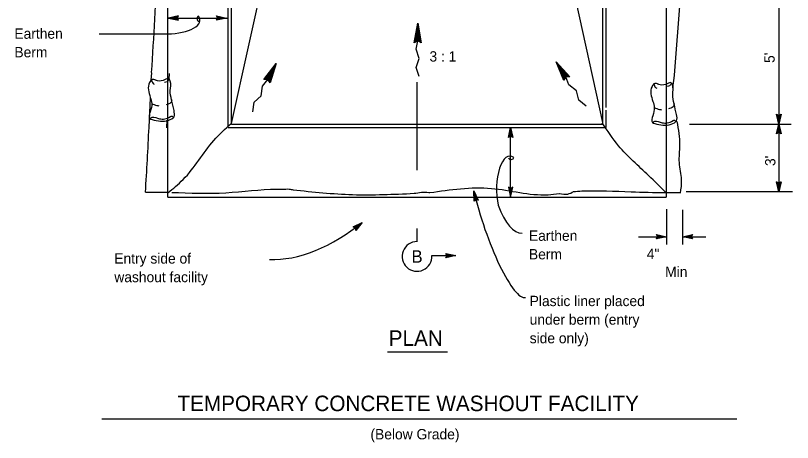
# Model space of a CAD drawing. Extents: x 6708826 to 6711089, y 1868571 to 1869537.
# Drawn here: x 6708832 to 6709283.4, y 1868571 to 1868819.1 of the extents above; entities that cross this region are included whole.
import ezdxf

# ---------------------------------------------------------------- set-up
doc = ezdxf.new("R2010")
doc.units = 0
for name, color, linetype in [('1 Control', 7, 'Continuous'), ('56 Stg 3 Anno', 7, 'Continuous'), ('57 Undefined', 7, 'Continuous'), ('60 Nongeo Data', 7, 'Continuous')]:
    doc.layers.add(name, color=color, linetype=linetype)

msp = doc.modelspace()

# ---------------------------------------------------------------- linework, layer by layer
at = {"layer": '1 Control'}
for p, q in [((6709274.17, 1868722.46), (6709274.17, 1868722.46)), ((6709276.73, 1868722.46), (6709276.73, 1868722.46)), ((6709098.33, 1868717.18), (6709098.33, 1868717.18)), ((6709275.45, 1868716.7), (6709275.45, 1868716.7)), ((6709098.34, 1868711.27), (6709098.34, 1868711.27)), ((6709100.84, 1868711.84), (6709100.84, 1868711.84)), ((6709204.39, 1868691.86), (6709204.39, 1868691.86)), ((6709225.36, 1868691.85), (6709225.36, 1868691.85)), ((6709204.39, 1868689.29), (6709204.39, 1868689.29)), ((6709210.15, 1868690.57), (6709210.15, 1868690.57)), ((6709219.6, 1868690.57), (6709219.6, 1868690.57)), ((6709225.36, 1868689.28), (6709225.36, 1868689.28))]:
    msp.add_line(p, q, dxfattribs=at)
for points in [[(6709276.73, 1868722.46), (6709275.45, 1868716.7), (6709274.17, 1868722.46), (6709274.51, 1868722.25), (6709275.44, 1868718.03), (6709276.39, 1868722.25), (6709276.05, 1868722.05), (6709275.45, 1868719.35), (6709274.85, 1868722.05), (6709275.19, 1868721.84), (6709275.45, 1868720.67), (6709275.71, 1868721.85), (6709275.45, 1868721.69), (6709274.17, 1868722.46), (6709275.45, 1868721.69)], [(6709098.34, 1868711.27), (6709098.33, 1868717.18), (6709100.84, 1868711.84), (6709100.46, 1868711.96), (6709098.63, 1868715.87), (6709098.63, 1868711.55), (6709098.91, 1868711.82), (6709098.91, 1868714.59), (6709100.09, 1868712.09), (6709099.71, 1868712.21), (6709099.2, 1868713.29), (6709099.2, 1868712.09), (6709099.43, 1868712.31), (6709100.84, 1868711.84), (6709099.43, 1868712.31)], [(6709204.39, 1868691.86), (6709210.15, 1868690.57), (6709204.39, 1868689.29), (6709204.6, 1868689.63), (6709208.82, 1868690.57), (6709204.6, 1868691.52), (6709204.8, 1868691.18), (6709207.5, 1868690.57), (6709204.8, 1868689.97), (6709205.01, 1868690.31), (6709206.17, 1868690.57), (6709205, 1868690.83), (6709205.16, 1868690.57), (6709204.39, 1868689.29), (6709205.16, 1868690.57)], [(6709225.36, 1868689.28), (6709219.6, 1868690.57), (6709225.36, 1868691.85), (6709225.15, 1868691.51), (6709220.93, 1868690.57), (6709225.15, 1868689.62), (6709224.95, 1868689.96), (6709222.25, 1868690.57), (6709224.95, 1868691.17), (6709224.74, 1868690.83), (6709223.58, 1868690.57), (6709224.75, 1868690.31), (6709224.59, 1868690.57), (6709225.36, 1868691.85), (6709224.59, 1868690.57)]]:
    msp.add_lwpolyline(points, close=True, dxfattribs=at)
for centre, major_axis in [((6708938.43, 1868817.2), (0.09, -1.51)), ((6709119.92, 1868736.43), (1.51, 0.09))]:
    msp.add_ellipse(centre, major_axis=major_axis, ratio=0.650992, start_param=3.141593, end_param=6.283185, dxfattribs=at)
at = {"layer": '56 Stg 3 Anno'}
for p, q in [((6709275.45, 1868833.28), (6709275.45, 1868756.03)), ((6708926.63, 1868818.88), (6708920.87, 1868817.59)), ((6708926.42, 1868818.54), (6708922.19, 1868817.59)), ((6708926.2, 1868818.19), (6708923.52, 1868817.59)), ((6708926.03, 1868817.86), (6708924.85, 1868817.59)), ((6708925.86, 1868817.59), (6708926.63, 1868818.88)), ((6708926.63, 1868818.88), (6708926.63, 1868818.88)), ((6708949.46, 1868817.59), (6708948.69, 1868818.88)), ((6708948.69, 1868818.88), (6708948.69, 1868818.88)), ((6708948.69, 1868818.88), (6708954.45, 1868817.59)), ((6708948.9, 1868818.54), (6708953.13, 1868817.59)), ((6708949.13, 1868818.19), (6708951.8, 1868817.59)), ((6708949.3, 1868817.86), (6708950.48, 1868817.59)), ((6708920.43, 1868817.59), (6708955.21, 1868817.59)), ((6708920.87, 1868817.59), (6708920.87, 1868817.59)), ((6708920.87, 1868817.59), (6708926.63, 1868816.31)), ((6708922.2, 1868817.59), (6708926.4, 1868816.66)), ((6708923.52, 1868817.59), (6708926.23, 1868816.99)), ((6708924.85, 1868817.59), (6708926.01, 1868817.34)), ((6708926.63, 1868816.31), (6708925.86, 1868817.59)), ((6708926.63, 1868816.31), (6708926.63, 1868816.31)), ((6708954.45, 1868817.59), (6708948.69, 1868816.31)), ((6708948.69, 1868816.31), (6708949.46, 1868817.59)), ((6708948.69, 1868816.31), (6708948.69, 1868816.31)), ((6708953.12, 1868817.59), (6708948.92, 1868816.66)), ((6708951.8, 1868817.59), (6708949.09, 1868816.99)), ((6708950.48, 1868817.59), (6708949.32, 1868817.34)), ((6708954.45, 1868817.59), (6708954.45, 1868817.59)), ((6709063.57, 1868803.19), (6709065.61, 1868814.73)), ((6709065.61, 1868814.73), (6709067.65, 1868803.19)), ((6709064.11, 1868803.51), (6709065.61, 1868811.97)), ((6709064.66, 1868803.82), (6709065.61, 1868809.23)), ((6709065.61, 1868811.97), (6709067.11, 1868803.51)), ((6709065.61, 1868809.23), (6709066.56, 1868803.82)), ((6708880.5, 1868808.48), (6708920.43, 1868808.48)), ((6709065.61, 1868804.37), (6709063.57, 1868803.19)), ((6709065.21, 1868804.14), (6709065.61, 1868806.43)), ((6709065.61, 1868806.43), (6709066.01, 1868804.14)), ((6709067.65, 1868803.19), (6709065.61, 1868804.37)), ((6708976.21, 1868781.88), (6708983.33, 1868791.19)), ((6708983.33, 1868791.19), (6708979.83, 1868780)), ((6709150.57, 1868781.35), (6709146.1, 1868792.18)), ((6709146.1, 1868792.18), (6709154.01, 1868783.53)), ((6708976.84, 1868781.91), (6708982.06, 1868788.74)), ((6708977.47, 1868781.94), (6708980.8, 1868786.31)), ((6708980.8, 1868786.31), (6708979.16, 1868781.06)), ((6708982.06, 1868788.74), (6708979.5, 1868780.53)), ((6709150.85, 1868781.9), (6709147.58, 1868789.85)), ((6709147.58, 1868789.85), (6709153.38, 1868783.51)), ((6709151.14, 1868782.46), (6709149.05, 1868787.54)), ((6709149.05, 1868787.54), (6709152.75, 1868783.48)), ((6708978.57, 1868781.99), (6708976.21, 1868781.88)), ((6708978.1, 1868781.97), (6708979.51, 1868783.81)), ((6708979.83, 1868780), (6708978.57, 1868781.99)), ((6708979.51, 1868783.81), (6708978.82, 1868781.6)), ((6709151.43, 1868783.03), (6709150.55, 1868785.17)), ((6709150.55, 1868785.17), (6709152.12, 1868783.46)), ((6709151.65, 1868783.44), (6709150.57, 1868781.35)), ((6709154.01, 1868783.53), (6709151.65, 1868783.44)), ((6709065.3, 1868729.14), (6709065.3, 1868780.38)), ((6709275.45, 1868756.03), (6709274.17, 1868761.79)), ((6709274.17, 1868761.79), (6709274.17, 1868761.79)), ((6709274.17, 1868761.79), (6709275.45, 1868761.02)), ((6709275.44, 1868757.36), (6709274.51, 1868761.56)), ((6709275.45, 1868758.68), (6709274.85, 1868761.39)), ((6709275.45, 1868760.01), (6709275.19, 1868761.17)), ((6709275.45, 1868761.02), (6709276.73, 1868761.79)), ((6709276.73, 1868761.79), (6709275.45, 1868756.03)), ((6709276.39, 1868761.58), (6709275.45, 1868757.35)), ((6709276.05, 1868761.35), (6709275.45, 1868758.68)), ((6709275.71, 1868761.19), (6709275.45, 1868760.01)), ((6709276.73, 1868761.79), (6709276.73, 1868761.79)), ((6709223.56, 1868756.03), (6709282.65, 1868756.03)), ((6709274.16, 1868750.27), (6709275.45, 1868756.03)), ((6709274.16, 1868750.27), (6709275.45, 1868756.03)), ((6709274.5, 1868750.47), (6709275.45, 1868754.7)), ((6709274.5, 1868750.47), (6709275.45, 1868754.7)), ((6709275.45, 1868756.03), (6709275.45, 1868716.7)), ((6709275.45, 1868756.03), (6709275.45, 1868756.03)), ((6709275.45, 1868756.03), (6709275.45, 1868756.03)), ((6709275.45, 1868756.03), (6709276.72, 1868750.27)), ((6709275.45, 1868756.03), (6709275.45, 1868756.03)), ((6709275.45, 1868756.03), (6709276.72, 1868750.27)), ((6709275.45, 1868754.69), (6709276.38, 1868750.49)), ((6709275.45, 1868754.69), (6709276.38, 1868750.49)), ((6709118.34, 1868748.18), (6709119.63, 1868753.94)), ((6709118.69, 1868748.39), (6709119.63, 1868752.62)), ((6709119.03, 1868748.61), (6709119.63, 1868751.29)), ((6709119.63, 1868753.94), (6709119.63, 1868753.94)), ((6709119.63, 1868753.94), (6709120.91, 1868748.18)), ((6709119.63, 1868713.59), (6709119.63, 1868753.09)), ((6709119.63, 1868752.61), (6709120.56, 1868748.41)), ((6709119.63, 1868751.29), (6709120.23, 1868748.58)), ((6709275.45, 1868751.03), (6709274.16, 1868750.27)), ((6709275.45, 1868751.03), (6709274.16, 1868750.27)), ((6709274.16, 1868750.27), (6709274.16, 1868750.27)), ((6709274.16, 1868750.27), (6709274.16, 1868750.27)), ((6709274.85, 1868750.7), (6709275.45, 1868753.37)), ((6709274.85, 1868750.7), (6709275.45, 1868753.37)), ((6709275.18, 1868750.87), (6709275.44, 1868752.05)), ((6709275.18, 1868750.87), (6709275.44, 1868752.05)), ((6709275.44, 1868752.05), (6709275.7, 1868750.89)), ((6709275.44, 1868752.05), (6709275.7, 1868750.89)), ((6709275.45, 1868753.37), (6709276.05, 1868750.66)), ((6709275.45, 1868753.37), (6709276.05, 1868750.66)), ((6709276.72, 1868750.27), (6709275.45, 1868751.03)), ((6709276.72, 1868750.27), (6709275.45, 1868751.03)), ((6709276.72, 1868750.27), (6709276.72, 1868750.27)), ((6709276.72, 1868750.27), (6709276.72, 1868750.27)), ((6709119.63, 1868748.95), (6709118.34, 1868748.18)), ((6709118.34, 1868748.18), (6709118.34, 1868748.18)), ((6709119.36, 1868748.78), (6709119.63, 1868749.96)), ((6709119.63, 1868749.96), (6709119.88, 1868748.8)), ((6709120.91, 1868748.18), (6709119.63, 1868748.95)), ((6709120.91, 1868748.18), (6709120.91, 1868748.18)), ((6709119.63, 1868718.57), (6709118.34, 1868719.34)), ((6709118.34, 1868719.34), (6709118.34, 1868719.34)), ((6709118.34, 1868719.34), (6709119.63, 1868713.58)), ((6709118.69, 1868719.13), (6709119.63, 1868714.91)), ((6709119.03, 1868718.91), (6709119.63, 1868716.23)), ((6709119.36, 1868718.74), (6709119.63, 1868717.56)), ((6709119.63, 1868713.58), (6709120.91, 1868719.34)), ((6709120.91, 1868719.34), (6709119.63, 1868718.57)), ((6709119.63, 1868714.92), (6709120.56, 1868719.12)), ((6709119.63, 1868716.23), (6709120.23, 1868718.95)), ((6709119.63, 1868717.56), (6709119.88, 1868718.72)), ((6709120.91, 1868719.34), (6709120.91, 1868719.34)), ((6709221.6, 1868716.82), (6709283.37, 1868716.82)), ((6709119.63, 1868713.58), (6709119.63, 1868713.58)), ((6709210.27, 1868706.48), (6709210.27, 1868686.06)), ((6709219.46, 1868706.23), (6709219.46, 1868686.06)), ((6709028.12, 1868696.23), (6709033.38, 1868698.91)), ((6709029.53, 1868695.73), (6709028.12, 1868696.23)), ((6709028.12, 1868696.23), (6709028.12, 1868696.23)), ((6709028.5, 1868696.1), (6709032.36, 1868698.07)), ((6709028.89, 1868695.97), (6709031.34, 1868697.22)), ((6709029.24, 1868695.83), (6709030.31, 1868696.38)), ((6709030.31, 1868696.38), (6709029.58, 1868695.44)), ((6709031.34, 1868697.22), (6709029.63, 1868695.03)), ((6709032.35, 1868698.06), (6709029.71, 1868694.66)), ((6709033.38, 1868698.91), (6709029.76, 1868694.25)), ((6709033.38, 1868698.91), (6709033.38, 1868698.91)), ((6709029.76, 1868694.25), (6709029.53, 1868695.73)), ((6709029.76, 1868694.25), (6709029.76, 1868694.25)), ((6709065.18, 1868695.4), (6709065.18, 1868687.67)), ((6709194, 1868690.57), (6709210.15, 1868690.57)), ((6709219.6, 1868690.57), (6709233.02, 1868690.57)), ((6709073.81, 1868679.6), (6709087.74, 1868679.6)), ((6709082.74, 1868679.6), (6709081.97, 1868680.89)), ((6709081.97, 1868680.89), (6709081.97, 1868680.89)), ((6709081.97, 1868680.89), (6709087.74, 1868679.6)), ((6709087.74, 1868679.6), (6709081.98, 1868678.32)), ((6709081.98, 1868678.32), (6709082.74, 1868679.6)), ((6709081.98, 1868678.32), (6709081.98, 1868678.32)), ((6709082.18, 1868680.55), (6709086.41, 1868679.6)), ((6709086.4, 1868679.6), (6709082.2, 1868678.67)), ((6709085.08, 1868679.6), (6709082.37, 1868679)), ((6709082.41, 1868680.2), (6709085.08, 1868679.6)), ((6709082.58, 1868679.87), (6709083.76, 1868679.6)), ((6709083.76, 1868679.6), (6709082.6, 1868679.35)), ((6709087.74, 1868679.6), (6709087.74, 1868679.6))]:
    msp.add_line(p, q, dxfattribs=at)
for points in [[(6709066.56, 1868783.6), (6709064.66, 1868788.88), (6709066.56, 1868794.17), (6709064.66, 1868799.45), (6709065.61, 1868804.37), (6709065.61, 1868814.73)], [(6708969.86, 1868763.1), (6708970.6, 1868768.67), (6708974.72, 1868772.49), (6708975.46, 1868778.06), (6708978.57, 1868781.99), (6708983.33, 1868791.19)], [(6709163.58, 1868766.41), (6709159.15, 1868769.85), (6709157.92, 1868775.33), (6709153.48, 1868778.77), (6709151.65, 1868783.44), (6709146.1, 1868792.18)]]:
    msp.add_lwpolyline(points, dxfattribs=at)
msp.add_arc((6709065.19, 1868679.08), 8.62, 90.1055, 3.4975, dxfattribs=at)
for centre, major_axis, ratio, start_param, end_param in [((6708920.69, 1868816.3), (18.45, 0.17), 0.4237, 4.694534, 6.575355), ((6709119.24, 1868717.91), (-0.1, 19.46), 0.39962, 5.985478, 8.337803), ((6709113.29, 1868700.75), (-14.99, 45.46), 0.209097, 1.133039, 3.129396), ((6709123.13, 1868740.37), (-3.31, 47.75), 0.350985, 2.267971, 3.129396), ((6709008.27, 1868723.75), (-49.44, -37.09), 0.567237, 0.604321, 1.654632)]:
    msp.add_ellipse(centre, major_axis=major_axis, ratio=ratio, start_param=start_param, end_param=end_param, dxfattribs=at)
at = {"layer": '57 Undefined'}
for p, q in [((6709048.02, 1868623.64), (6709083.03, 1868623.64)), ((6708882.08, 1868584.74), (6709251, 1868584.74))]:
    msp.add_line(p, q, dxfattribs=at)
at = {"layer": '60 Nongeo Data'}
for p, q in [((6709218.56, 1868836.41), (6709214.73, 1868784.37)), ((6708910.85, 1868781.61), (6708911.06, 1868785.86)), ((6708921.22, 1868782.08), (6708921.38, 1868785.35)), ((6709214.54, 1868784.28), (6709213.72, 1868777.01)), ((6708909.52, 1868754.31), (6708910.33, 1868771.01)), ((6708919.84, 1868753.8), (6708920.05, 1868758.26)), ((6708957.34, 1868756.03), (6709173.02, 1868756.03)), ((6708955.42, 1868754.11), (6709174.94, 1868754.11)), ((6708907.42, 1868716.46), (6708919.91, 1868716.37)), ((6709210.02, 1868716.31), (6709218.11, 1868716.18)), ((6708920.45, 1868713.46), (6709209.91, 1868713.46))]:
    msp.add_line(p, q, dxfattribs=at)
for points in [[(6708920.45, 1868713.46), (6708920.45, 1869094.08), (6709209.91, 1869094.08), (6709209.91, 1868713.46)], [(6708955.42, 1868754.11), (6708955.42, 1869059.11), (6709174.94, 1869059.11), (6709174.94, 1868765.65)], [(6708957.34, 1868756.03), (6708957.34, 1869057.19), (6709173.02, 1869057.19), (6709173.02, 1868756.03)], [(6708957.38, 1868756.31), (6708987.05, 1868890.2)], [(6709143.66, 1868890.2), (6709172.98, 1868757)], [(6709174.94, 1868764.06), (6709174.94, 1868754.11)]]:
    msp.add_lwpolyline(points, dxfattribs=at)
for points in [[(6708911.04, 1868785.99), (6708914.48, 1868847.99), (6708914.52, 1868848.93)], [(6708913.44, 1868781.48), (6708911.4, 1868781.86), (6708909.81, 1868780.2), (6708910.26, 1868771.52), (6708911.1, 1868767.97), (6708910.19, 1868763.21), (6708910.04, 1868759.29), (6708911.32, 1868758.68), (6708920.93, 1868758.3), (6708924.03, 1868760.27), (6708924.03, 1868763.89), (6708922.6, 1868770.08), (6708921.84, 1868775.52), (6708921.76, 1868781.03), (6708920.7, 1868782.39), (6708918.89, 1868781.86), (6708914.43, 1868781.1), (6708913.21, 1868781.56)], [(6708921.23, 1868782.24), (6708920.02, 1868780.58), (6708918.43, 1868780.2)], [(6708910.87, 1868781.63), (6708911.85, 1868779.67), (6708912.53, 1868779.22)], [(6709205.43, 1868779.15), (6709203.38, 1868779.53), (6709201.79, 1868777.87), (6709202.25, 1868769.19), (6709203.08, 1868765.64), (6709202.17, 1868760.88), (6709202.02, 1868756.96), (6709203.31, 1868756.35), (6709212.92, 1868755.98), (6709216.02, 1868757.94), (6709216.02, 1868761.56), (6709214.58, 1868767.75), (6709213.82, 1868773.19), (6709213.75, 1868778.7), (6709212.69, 1868780.06), (6709210.87, 1868779.53), (6709206.41, 1868778.78), (6709205.2, 1868779.23)], [(6709202.85, 1868779.3), (6709203.84, 1868777.34), (6709204.52, 1868776.89)], [(6709213.22, 1868779.91), (6709212.01, 1868778.25), (6709210.42, 1868777.87)], [(6708922.67, 1868770.16), (6708921.54, 1868767.89), (6708920.63, 1868767.59), (6708919.42, 1868767.21)], [(6708911.02, 1868767.97), (6708914.05, 1868766.84), (6708915.26, 1868766.68)], [(6709203.01, 1868765.64), (6709206.03, 1868764.51), (6709207.24, 1868764.36)], [(6709214.66, 1868767.83), (6709213.52, 1868765.56), (6709212.61, 1868765.26), (6709211.4, 1868764.88)], [(6708909.96, 1868759.29), (6708911.32, 1868759.96), (6708915.64, 1868759.13), (6708918.66, 1868758.98), (6708921.99, 1868760.34), (6708922.9, 1868760.57), (6708923.73, 1868759.59)], [(6708907.43, 1868716.48), (6708909.51, 1868754.03), (6708909.55, 1868754.96)], [(6708920.4, 1868716.06), (6708929.33, 1868723.79), (6708947.19, 1868746.45), (6708957.25, 1868756.43)], [(6709209.65, 1868716.38), (6709199.89, 1868726.02), (6709182.33, 1868743.4), (6709172.8, 1868756.75)], [(6709201.95, 1868756.96), (6709203.31, 1868757.64), (6709207.62, 1868756.81), (6709210.65, 1868756.66), (6709213.97, 1868758.01), (6709214.88, 1868758.24), (6709215.71, 1868757.26)], [(6709216.18, 1868757.56), (6709217.79, 1868743.66), (6709217.47, 1868733.64), (6709218.76, 1868723.62), (6709218.12, 1868715.91)], [(6709072.66, 1868716.2), (6709108.46, 1868718.65), (6709141.34, 1868714.95), (6709147.79, 1868715.58)], [(6708922.69, 1868716.35), (6708954.23, 1868716.13), (6708983.7, 1868718.16), (6708987.22, 1868718.11)], [(6708987.22, 1868718.11), (6708990.96, 1868718.24), (6708993.28, 1868717.81)], [(6708993.28, 1868717.81), (6709027.81, 1868715.05), (6709063.48, 1868715.77)], [(6709063.48, 1868715.77), (6709072.06, 1868716.3), (6709072.66, 1868716.2)], [(6709148.04, 1868715.58), (6709152.77, 1868715.33), (6709156.34, 1868716.84)], [(6709155.99, 1868716.83), (6709161.07, 1868717.14), (6709189.58, 1868716.65), (6709209.56, 1868716.17)]]:
    msp.add_spline(points, degree=3, dxfattribs=at)

# ---------------------------------------------------------------- texts
at = {"layer": '57 Undefined'}
for s, height, p in [('Earthen', 6, (6708831.3, 1868805.59)), ('Berm', 6, (6708831.3, 1868794.79)), ('Earthen', 6, (6709130.28, 1868688.19)), ('B', 7.21, (6709062.06, 1868675.48)), ('Berm', 6, (6709130.28, 1868677.39)), ('4"', 6, (6709198.74, 1868677.63)), ('Entry side of', 6, (6708889.34, 1868674.94)), ('Min', 6, (6709209.42, 1868667.19)), ('washout facility', 6, (6708889.34, 1868664.14)), ('Plastic liner placed ', 6, (6709130.69, 1868650.24)), ('under berm (entry ', 6, (6709130.69, 1868639.44)), ('PLAN', 9, (6709048.76, 1868627.16)), ('side only)', 6, (6709130.69, 1868628.64)), ('TEMPORARY CONCRETE WASHOUT FACILITY', 9, (6708926.01, 1868589.22)), ('(Below Grade)', 6, (6709038.17, 1868572.82))]:
    msp.add_text(s, height=height, dxfattribs=at).set_placement(p)
for s, rotation, p in [('3 : 1', 359.9387, (6709072.45, 1868792.33)), ("5'", 90, (6709273.05, 1868791.52)), ("3'", 90, (6709273.47, 1868731.65))]:
    msp.add_text(s, height=6, rotation=rotation, dxfattribs=at).set_placement(p)

doc.saveas('drawing.dxf')
